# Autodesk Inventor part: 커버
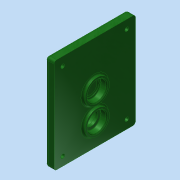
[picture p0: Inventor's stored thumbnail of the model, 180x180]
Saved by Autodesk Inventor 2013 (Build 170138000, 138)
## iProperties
Created: 2016-02
Part Number: 커버
Material: 알루미늄 6061
Document SubType Name: Modeling
Designer: mduedu
Density: 2.71 g/cm^3
Mass: 272.254 g
Surface Area: 266.629 cm^2
Volume: 100.463 cm^3
Author: mduedu
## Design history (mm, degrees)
sketch "스케치1"
  geometry: L1 (63, 47)-(-47, 47); L2 (-47, 47)-(-47, -47); L3 (-47, -47)-(63, -47); L4 (63, -47)-(63, 47); 2 further points
  constraints: 8 end point, 2 parallel, 1 horizontal, 1 horizontal alignment, 1 midpoint, 1 perpendicular
  dimensions: "d102" = 94 distance of L3.end L1.start; "d104" = 47 distance from line of L2 point (0, 0); "d105" = 110 distance of L1.start L1.end
extrude "돌출1" new body sketch "스케치1" distance "d1" = 10; taper "d2" = 0 deg
sketch "스케치2"
  geometry: C1 r 14 at (0, 11); 1 further point
  constraints: 1 centre point, 1 vertical alignment
  dimensions: "d3" = 28 diameter of C1; "d6" = 11 distance of C1.centre point (0, 0)
extrude "돌출2" join sketch "스케치2" distance "d7" = 3; taper "d8" = 0 deg
sketch "스케치3"
  geometry: C1 r 14 at (0, -20); 1 further point
  constraints: 1 centre point, 1 vertical alignment
  dimensions: "d9" = 28 diameter of C1; "d10" = 20 distance of C1.centre point (0, 0)
extrude "돌출3" join sketch "스케치3" distance "d11" = 3; taper "d12" = 0 deg
hole "구멍1" diameter "d15" = 22; stored, may be unused: countersink angle "d19" = 90 deg, drill point angle "d21" = 0 deg; dims "d13" = 10, "d14" = 10, "d16" = 6, "d17" = 4, "d18" = 2, "d20" = 7
hole "구멍2" diameter "d24" = 18; stored, may be unused: countersink angle "d28" = 90 deg, drill point angle "d30" = 0 deg; dims "d22" = 10, "d23" = 10, "d25" = 6, "d26" = 4, "d27" = 2, "d29" = 1
hole "구멍3" diameter "d33" = 22; stored, may be unused: countersink angle "d37" = 90 deg, drill point angle "d39" = 0 deg; dims "d34" = 6, "d35" = 4, "d36" = 2, "d38" = 7, "d73" = 10, "d74" = 10
sketch "스케치4"
  geometry: C1 r 14 at (0, -20) reference; C2 r 18 at (0, -20); 1 further point
  constraints: 1 centre point, 1 coincident
  dimensions: "d40" = 36 diameter of C2
extrude "돌출4" join sketch "스케치4" distance "d41" = 4; taper "d42" = 0 deg
hole "구멍4" diameter "d45" = 22; stored, may be unused: countersink angle "d49" = 90 deg, drill point angle "d51" = 0 deg; dims "d43" = 10, "d44" = 10, "d46" = 6, "d47" = 4, "d48" = 2, "d50" = 7
hole "구멍5" diameter "d54" = 15; stored, may be unused: countersink angle "d58" = 90 deg, drill point angle "d60" = 0 deg; dims "d52" = 10, "d53" = 10, "d55" = 6, "d56" = 4, "d57" = 2, "d59" = 7
fillet "모깎기1" dims "d61" = 0.3
fillet "모깎기2" dims "d62" = 2
chamfer "모따기1" distance "d63" = 1; stored, may be unused: second distance "d64" = 2, angle "d65" = 45 deg
fillet "모깎기6" dims "d88" = 2
fillet "모깎기4" dims "d75" = 2
sketch "스케치9"
  geometry: L1 (47, 63)-(47, -47) reference; L2 (-47, 63)-(47, 63) reference; L3 (-47, -47)-(-47, 63) reference; L4 (47, -47)-(-47, -47) reference; L5 (37, 53)-(37, -37); L6 (37, -37)-(-37, -37); L7 (-37, -37)-(-37, 53); L8 (-37, 53)-(37, 53); C1 r 20 at (0, -20) reference; 5 further points
  constraints: 8 end point, 4 coincident, 3 other
  dimensions: "d107" = 10 distance between parallel lines of L8 L2
hole "구멍7" sketch "스케치9" at (-37, 53), (37, 53), (37, -37), (-37, -37) diameter "d108" = 4.5; stored, may be unused: countersink angle "d112" = 90 deg, drill point angle "d114" = 118 deg; dims "d109" = 6, "d110" = 8, "d111" = 4.6, "d113" = 8
fillet "모깎기8" dims "d106" = 3
fillet "모깎기9" dims "d115" = 3
node "솔리드1"
node "투영된 루프2"
